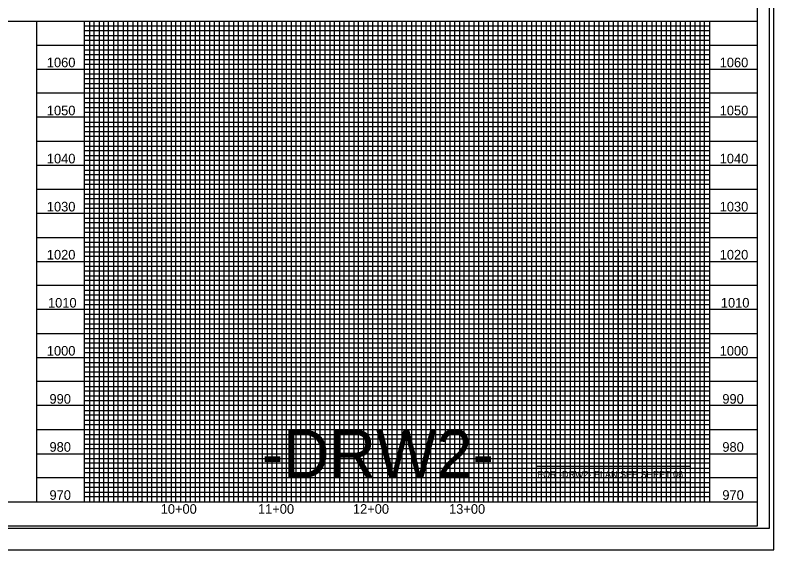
# Model space of a CAD drawing. Extents: x 1260439 to 1262228, y 742196 to 743296.
# Drawn here: x 1261333 to 1262123, y 742196 to 742752 of the extents above; entities that cross this region are included whole.
import ezdxf

# ---------------------------------------------------------------- set-up
doc = ezdxf.new("R2010")
doc.units = 0
for name, color, linetype in [('Exist Vertical Profile Horizontal Axis Label Major', 7, 'Continuous'), ('Exist Vertical Profile Vertical Axis Label', 7, 'Continuous'), ('Prop Grid Mask', 7, 'Continuous'), ('Prop PFL Text', 7, 'Continuous'), ('Sheet Data Field CELL', 7, 'Continuous'), ('Sheet Plot Border Inside CELL', 7, 'Continuous'), ('Sheet Plot Border Outside CELL', 7, 'Continuous'), ('Sheet Profile CELL', 7, 'Continuous'), ('Sheet Profile Grid Major CELL', 7, 'Continuous'), ('Sheet Profile Grid Middle CELL', 7, 'Continuous'), ('Sheet Profile Grid Minor CELL', 7, 'Continuous')]:
    doc.layers.add(name, color=color, linetype=linetype)

msp = doc.modelspace()

# ---------------------------------------------------------------- linework, layer by layer
at = {"layer": 'Prop Grid Mask'}
msp.add_lwpolyline([(1261875.75, 742282.74), (1262035.75, 742282.74), (1262035.75, 742265.74), (1261875.75, 742265.74)], close=True, dxfattribs=at)
at = {"layer": 'Sheet Plot Border Inside CELL'}
msp.add_lwpolyline([(1260451.75, 742218.19), (1262118.25, 742218.19), (1262118.25, 743273.29), (1260451.75, 743273.29)], close=True, dxfattribs=at)
at = {"layer": 'Sheet Plot Border Outside CELL'}
msp.add_lwpolyline([(1260438.75, 742195.74), (1262122.75, 742195.74), (1262122.75, 743295.74), (1260438.75, 743295.74)], close=True, dxfattribs=at)
at = {"layer": 'Sheet Profile CELL'}
for p, q in [((1260605.75, 742745.74), (1262105.75, 742745.74)), ((1260605.75, 742245.74), (1262105.75, 742245.74))]:
    msp.add_line(p, q, dxfattribs=at)
msp.add_lwpolyline([(1262105.75, 743270.74), (1260605.75, 743270.74), (1260605.75, 742220.74), (1262105.75, 742220.74)], close=True, dxfattribs=at)
at = {"layer": 'Sheet Profile Grid Major CELL'}
for p, q in [((1261305.75, 742745.74), (1261355.75, 742745.74)), ((1261355.75, 742745.74), (1261355.75, 742245.74)), ((1261405.75, 742745.74), (1261455.75, 742745.74)), ((1261405.75, 742245.74), (1261405.75, 742745.74)), ((1261405.75, 742745.74), (1261455.75, 742745.74)), ((1261455.75, 742745.74), (1261455.75, 742245.74)), ((1261505.75, 742745.74), (1261555.75, 742745.74)), ((1261505.75, 742245.74), (1261505.75, 742745.74)), ((1261505.75, 742745.74), (1261555.75, 742745.74)), ((1261555.75, 742745.74), (1261555.75, 742245.74)), ((1261605.75, 742745.74), (1261655.75, 742745.74)), ((1261605.75, 742245.74), (1261605.75, 742745.74)), ((1261605.75, 742745.74), (1261655.75, 742745.74)), ((1261655.75, 742745.74), (1261655.75, 742245.74)), ((1261705.75, 742745.74), (1261755.75, 742745.74)), ((1261705.75, 742245.74), (1261705.75, 742745.74)), ((1261705.75, 742745.74), (1261755.75, 742745.74)), ((1261755.75, 742745.74), (1261755.75, 742245.74)), ((1261805.75, 742745.74), (1261855.75, 742745.74)), ((1261805.75, 742245.74), (1261805.75, 742745.74)), ((1261855.75, 742745.74), (1261855.75, 742245.74)), ((1261905.75, 742745.74), (1261955.75, 742745.74)), ((1261905.75, 742245.74), (1261905.75, 742745.74)), ((1262005.75, 742745.74), (1262055.75, 742745.74)), ((1261355.75, 742245.74), (1261405.75, 742245.74)), ((1261455.75, 742245.74), (1261505.75, 742245.74)), ((1261555.75, 742245.74), (1261605.75, 742245.74)), ((1261655.75, 742245.74), (1261705.75, 742245.74)), ((1261755.75, 742245.74), (1261805.75, 742245.74)), ((1261855.75, 742245.74), (1261905.75, 742245.74))]:
    msp.add_line(p, q, dxfattribs=at)
for points in [[(1261955.75, 742745.74), (1261955.75, 742245.74), (1262005.75, 742245.74), (1262005.75, 742245.74), (1262005.75, 742745.74)], [(1262055.75, 742745.74), (1262055.75, 742245.74), (1262105.75, 742245.74), (1262105.75, 742740.74)], [(1261355.75, 742695.74), (1262105.75, 742695.74)], [(1262105.75, 742645.74), (1261355.75, 742645.74)], [(1261355.75, 742595.74), (1262105.75, 742595.74)], [(1262105.75, 742545.74), (1261355.75, 742545.74)], [(1261355.75, 742495.74), (1262105.75, 742495.74)], [(1262105.75, 742445.74), (1261355.75, 742445.74)], [(1261355.75, 742395.74), (1262105.75, 742395.74)], [(1262105.75, 742345.74), (1261355.75, 742345.74)], [(1261355.75, 742295.74), (1262105.75, 742295.74)]]:
    msp.add_lwpolyline(points, dxfattribs=at)
at = {"layer": 'Sheet Profile Grid Middle CELL'}
for p, q in [((1261430.75, 742245.74), (1261430.75, 742745.74)), ((1261430.75, 742745.74), (1261480.75, 742745.74)), ((1261480.75, 742745.74), (1261480.75, 742245.74)), ((1261530.75, 742245.74), (1261530.75, 742745.74)), ((1261530.75, 742745.74), (1261580.75, 742745.74)), ((1261580.75, 742745.74), (1261580.75, 742245.74)), ((1261630.75, 742245.74), (1261630.75, 742745.74)), ((1261630.75, 742745.74), (1261680.75, 742745.74)), ((1261680.75, 742745.74), (1261680.75, 742245.74)), ((1261730.75, 742245.74), (1261730.75, 742745.74)), ((1261730.75, 742745.74), (1262055.75, 742745.74)), ((1261780.75, 742745.74), (1261780.75, 742245.74)), ((1261830.75, 742245.74), (1261830.75, 742745.74)), ((1261880.75, 742745.74), (1261880.75, 742245.74)), ((1261930.75, 742245.74), (1261930.75, 742745.74)), ((1261355.75, 742720.74), (1262105.75, 742720.74)), ((1261380.75, 742245.74), (1261430.75, 742245.74)), ((1261480.75, 742245.74), (1261530.75, 742245.74)), ((1261580.75, 742245.74), (1261630.75, 742245.74)), ((1261680.75, 742245.74), (1261730.75, 742245.74)), ((1261780.75, 742245.74), (1261830.75, 742245.74)), ((1261880.75, 742245.74), (1261930.75, 742245.74))]:
    msp.add_line(p, q, dxfattribs=at)
for points in [[(1261930.75, 742508.54), (1261930.75, 742245.74), (1261980.75, 742245.74), (1261980.75, 742745.74)], [(1261980.75, 742508.54), (1261980.75, 742245.74), (1262030.75, 742245.74), (1262030.75, 742745.74)], [(1262105.75, 742670.74), (1261355.75, 742670.74)], [(1261355.75, 742620.74), (1262105.75, 742620.74)], [(1262105.75, 742570.74), (1261355.75, 742570.74)], [(1261355.75, 742520.74), (1261930.75, 742520.74)], [(1261930.75, 742520.74), (1262105.75, 742520.74)], [(1262105.75, 742470.74), (1261355.75, 742470.74)], [(1261355.75, 742420.74), (1262105.75, 742420.74)], [(1262105.75, 742370.74), (1261355.75, 742370.74)], [(1261355.75, 742320.74), (1262105.75, 742320.74)], [(1262105.75, 742270.74), (1261355.75, 742270.74)]]:
    msp.add_lwpolyline(points, dxfattribs=at)
at = {"layer": 'Sheet Profile Grid Minor CELL'}
for p, q in [((1261800.75, 742245.74), (1261800.75, 742745.74)), ((1261810.75, 742745.74), (1261810.75, 742245.74)), ((1261815.75, 742245.74), (1261815.75, 742745.74)), ((1261820.75, 742745.74), (1261820.75, 742245.74)), ((1261825.75, 742245.74), (1261825.75, 742745.74)), ((1261835.75, 742745.74), (1261835.75, 742245.74)), ((1261840.75, 742245.74), (1261840.75, 742745.74)), ((1261845.75, 742745.74), (1261845.75, 742245.74)), ((1261850.75, 742245.74), (1261850.75, 742745.74)), ((1261860.75, 742745.74), (1261860.75, 742245.74)), ((1261865.75, 742245.74), (1261865.75, 742745.74)), ((1261870.75, 742745.74), (1261870.75, 742245.74)), ((1261875.75, 742245.74), (1261875.75, 742745.74)), ((1261885.75, 742745.74), (1261885.75, 742245.74)), ((1261890.75, 742245.74), (1261890.75, 742745.74)), ((1261895.75, 742745.74), (1261895.75, 742245.74)), ((1261900.75, 742245.74), (1261900.75, 742745.74)), ((1261405.75, 742740.74), (1262055.75, 742740.74)), ((1262055.75, 742735.78), (1261405.75, 742735.6)), ((1261405.75, 742730.74), (1262055.75, 742730.74)), ((1262055.75, 742610.74), (1261405.75, 742610.74)), ((1262055.75, 742605.74), (1261405.75, 742605.74)), ((1262055.75, 742600.74), (1261405.75, 742600.74)), ((1261405.75, 742590.74), (1262055.75, 742590.74)), ((1262055.75, 742585.74), (1261405.75, 742585.74)), ((1261405.75, 742580.74), (1262055.75, 742580.74)), ((1262055.75, 742560.74), (1261405.75, 742560.74)), ((1261405.75, 742555.74), (1262055.75, 742555.74)), ((1262055.75, 742535.74), (1261405.75, 742535.74)), ((1261405.75, 742530.74), (1262055.75, 742530.74)), ((1262055.75, 742510.74), (1261405.75, 742510.74)), ((1261405.75, 742505.74), (1262055.75, 742505.74)), ((1262055.75, 742500.74), (1261405.75, 742500.74)), ((1261405.75, 742490.74), (1262055.75, 742490.74)), ((1262055.75, 742485.74), (1261405.75, 742485.74)), ((1261405.75, 742480.74), (1262055.75, 742480.74)), ((1262055.75, 742475.74), (1261405.75, 742475.74)), ((1261405.75, 742465.74), (1262055.75, 742465.74)), ((1262055.75, 742460.74), (1261405.75, 742460.74)), ((1261405.75, 742455.74), (1262055.75, 742455.74)), ((1262055.75, 742450.74), (1261405.75, 742450.74)), ((1261405.75, 742440.74), (1262055.75, 742440.74)), ((1262055.75, 742435.74), (1261405.75, 742435.74)), ((1261405.75, 742430.74), (1262055.75, 742430.74)), ((1262055.75, 742425.74), (1261405.75, 742425.74)), ((1261405.75, 742415.74), (1262055.75, 742415.74)), ((1262055.75, 742410.74), (1261405.75, 742410.74)), ((1261405.75, 742405.74), (1262055.75, 742405.74)), ((1262055.75, 742400.74), (1261405.75, 742400.74)), ((1261405.75, 742390.74), (1262055.75, 742390.74)), ((1262055.75, 742385.74), (1261405.75, 742385.74)), ((1261405.75, 742380.74), (1262055.75, 742380.74)), ((1262055.75, 742375.74), (1261405.75, 742375.74)), ((1261405.75, 742365.74), (1262055.75, 742365.74)), ((1262055.75, 742360.74), (1261405.75, 742360.74)), ((1262055.75, 742355.74), (1261405.75, 742355.74)), ((1262055.75, 742350.74), (1261405.75, 742350.74)), ((1261405.75, 742340.74), (1262055.75, 742340.74)), ((1262055.75, 742335.74), (1261405.75, 742335.74)), ((1261405.75, 742330.74), (1262055.75, 742330.74)), ((1262055.75, 742325.74), (1261405.75, 742325.74)), ((1261405.75, 742315.74), (1262055.75, 742315.74)), ((1262055.75, 742310.74), (1261405.75, 742310.74)), ((1261405.75, 742305.74), (1262055.75, 742305.74)), ((1262055.75, 742300.74), (1261405.75, 742300.74)), ((1261405.75, 742290.74), (1262055.75, 742290.74)), ((1262055.75, 742285.74), (1261405.75, 742285.74)), ((1261405.75, 742280.74), (1262055.75, 742280.74)), ((1262055.75, 742275.74), (1261405.75, 742275.74)), ((1261405.75, 742265.74), (1262055.75, 742265.74)), ((1262055.75, 742260.74), (1261405.75, 742260.74)), ((1261405.75, 742255.74), (1262055.75, 742255.74)), ((1261795.75, 742245.74), (1261800.75, 742245.74)), ((1261810.75, 742245.74), (1261815.75, 742245.74)), ((1261820.75, 742245.74), (1261825.75, 742245.74)), ((1261835.75, 742245.74), (1261840.75, 742245.74)), ((1261845.75, 742245.74), (1261850.75, 742245.74)), ((1261860.75, 742245.74), (1261865.75, 742245.74)), ((1261870.75, 742245.74), (1261875.75, 742245.74)), ((1261885.75, 742245.74), (1261890.75, 742245.74)), ((1261895.75, 742245.74), (1261900.75, 742245.74))]:
    msp.add_line(p, q, dxfattribs=at)
for points in [[(1261405.75, 742745.74), (1261410.75, 742745.74), (1261410.75, 742245.74), (1261415.75, 742245.74), (1261415.75, 742745.74), (1261420.75, 742745.74), (1261420.75, 742245.74), (1261425.75, 742245.74), (1261425.75, 742745.74), (1261435.75, 742745.74), (1261435.75, 742245.74), (1261440.75, 742245.74), (1261440.75, 742745.74), (1261445.75, 742745.74), (1261445.75, 742245.74), (1261450.75, 742245.74), (1261450.75, 742745.74), (1261460.75, 742745.74), (1261460.75, 742245.74), (1261465.45, 742246.29), (1261465.75, 742245.74), (1261465.75, 742745.74), (1261470.75, 742745.74), (1261470.75, 742245.74), (1261475.75, 742245.74), (1261475.75, 742745.74), (1261485.75, 742745.74), (1261485.75, 742245.74), (1261490.75, 742245.74)], [(1261490.75, 742245.74), (1261490.75, 742745.74), (1261495.75, 742745.74), (1261495.75, 742245.74), (1261500.75, 742245.74), (1261500.75, 742745.74), (1261510.75, 742745.74), (1261510.75, 742245.74), (1261515.75, 742245.74), (1261515.75, 742745.74), (1261520.75, 742745.74), (1261520.75, 742245.74), (1261525.75, 742245.74), (1261525.75, 742745.74), (1261535.75, 742745.74), (1261535.75, 742245.74), (1261540.75, 742245.74), (1261540.75, 742745.74), (1261545.75, 742745.74), (1261545.75, 742245.74), (1261550.75, 742245.74), (1261550.75, 742745.74), (1261560.75, 742745.74), (1261560.75, 742245.74), (1261565.75, 742245.74), (1261565.75, 742745.74), (1261570.75, 742745.74), (1261570.75, 742245.74), (1261575.75, 742245.74), (1261575.75, 742745.74), (1261585.75, 742745.74), (1261585.75, 742245.74), (1261590.75, 742245.74), (1261590.75, 742745.74), (1261595.75, 742745.74), (1261595.75, 742245.74), (1261600.75, 742245.74), (1261600.75, 742745.74), (1261610.75, 742745.74), (1261610.75, 742245.74), (1261615.75, 742245.74), (1261615.75, 742745.74), (1261620.75, 742745.74), (1261620.75, 742245.74), (1261625.75, 742245.74), (1261625.75, 742745.74), (1261635.75, 742745.74), (1261635.75, 742245.74), (1261640.75, 742245.74), (1261640.75, 742745.74), (1261645.75, 742745.74), (1261645.75, 742245.74), (1261650.75, 742245.74), (1261650.75, 742745.74), (1261660.75, 742745.74), (1261660.75, 742245.74), (1261665.75, 742245.74), (1261665.75, 742745.74), (1261670.75, 742745.74), (1261670.75, 742245.74), (1261675.75, 742245.74), (1261675.75, 742745.74), (1261685.75, 742745.74), (1261685.75, 742245.74), (1261690.75, 742245.74), (1261690.75, 742745.74), (1261695.75, 742745.74), (1261695.75, 742245.74), (1261700.75, 742245.74), (1261700.75, 742745.74), (1261710.75, 742745.74), (1261710.75, 742245.74), (1261715.75, 742245.74), (1261715.75, 742745.74), (1261720.75, 742745.74), (1261720.75, 742245.74), (1261725.75, 742245.74), (1261725.75, 742745.74), (1261735.75, 742745.74), (1261735.75, 742245.74), (1261740.75, 742245.74), (1261740.75, 742745.74), (1261745.75, 742745.74), (1261745.75, 742245.74), (1261750.75, 742245.74), (1261750.75, 742745.74), (1261760.75, 742745.74), (1261760.75, 742245.74), (1261765.75, 742245.74), (1261765.75, 742745.74), (1261770.75, 742745.74), (1261770.75, 742245.74), (1261775.75, 742245.74), (1261775.75, 742745.74), (1261785.75, 742745.74), (1261785.75, 742245.74), (1261790.75, 742245.74), (1261790.75, 742745.74), (1261795.75, 742745.74), (1261795.75, 742245.74)], [(1261910.75, 742745.74), (1261910.75, 742245.74), (1261915.75, 742245.74), (1261915.75, 742745.74)], [(1261920.75, 742745.74), (1261920.75, 742245.74), (1261925.75, 742245.74), (1261925.75, 742745.74)], [(1261935.75, 742745.74), (1261935.75, 742245.74), (1261935.75, 742245.74), (1261940.75, 742245.74), (1261945.75, 742245.74), (1261945.75, 742745.74)], [(1261940.75, 742745.74), (1261940.75, 742245.74)], [(1261950.79, 742745.74), (1261950.65, 742245.79), (1261955.65, 742245.79), (1261960.75, 742245.74), (1261960.75, 742745.74)], [(1261960.75, 742508.54), (1261960.75, 742245.74), (1261965.75, 742245.74), (1261965.75, 742745.74)], [(1261970.75, 742745.74), (1261970.75, 742245.74), (1261975.75, 742245.74), (1261975.75, 742745.74)], [(1261985.75, 742745.74), (1261985.75, 742245.74), (1261990.75, 742245.74), (1261990.75, 742745.74)], [(1261995.75, 742745.74), (1261995.75, 742245.74), (1262000.75, 742245.74), (1262000.75, 742745.74)], [(1262010.75, 742745.74), (1262010.75, 742245.74), (1262015.75, 742245.74), (1262015.75, 742745.74)], [(1262020.75, 742745.74), (1262020.75, 742245.74), (1262025.75, 742245.74), (1262025.75, 742745.74)], [(1262035.75, 742745.74), (1262035.75, 742245.74), (1262040.75, 742245.74), (1262040.75, 742745.74)], [(1262045.75, 742745.74), (1262045.75, 742245.74), (1262050.75, 742245.74), (1262050.75, 742745.74)], [(1262055.75, 742725.74), (1261405.75, 742725.74)], [(1261405.75, 742715.74), (1262055.75, 742715.74)], [(1262055.75, 742710.74), (1261405.75, 742710.74)], [(1261405.75, 742705.74), (1262055.75, 742705.74)], [(1262055.75, 742700.74), (1261405.75, 742700.74)], [(1261405.75, 742690.74), (1262055.75, 742690.74)], [(1262055.75, 742685.74), (1261405.75, 742685.74)], [(1261405.75, 742680.74), (1262055.75, 742680.74)], [(1262055.75, 742675.74), (1261405.75, 742675.74)], [(1261405.75, 742665.74), (1262055.75, 742665.74)], [(1262055.75, 742660.74), (1261405.75, 742660.74)], [(1261405.75, 742655.74), (1262055.75, 742655.74)], [(1262055.75, 742650.74), (1261405.75, 742650.74)], [(1261405.75, 742640.74), (1262055.75, 742640.74)], [(1262055.75, 742635.64), (1261405.75, 742635.64)], [(1261405.75, 742630.74), (1262055.75, 742630.74)], [(1262055.75, 742625.74), (1261405.75, 742625.74)], [(1261405.75, 742615.74), (1262055.75, 742615.74)], [(1262055.75, 742575.74), (1261405.75, 742575.74)], [(1261405.75, 742565.74), (1262055.75, 742565.74)], [(1262055.75, 742550.74), (1261405.75, 742550.74)], [(1261405.75, 742540.74), (1262055.75, 742540.74)], [(1262055.75, 742525.74), (1261405.75, 742525.74)], [(1261405.75, 742515.74), (1262055.75, 742515.74)], [(1262055.75, 742250.74), (1261405.75, 742250.74)]]:
    msp.add_lwpolyline(points, dxfattribs=at)

# ---------------------------------------------------------------- texts
at = {"layer": 'Exist Vertical Profile Horizontal Axis Label Major'}
for s, p in [('10+00', (1261484.88, 742233.24)), ('11+00', (1261586.08, 742233.24)), ('12+00', (1261684.88, 742233.24)), ('13+00', (1261784.88, 742233.24))]:
    msp.add_text(s, height=10, dxfattribs=at).set_placement(p)
at = {"layer": 'Exist Vertical Profile Vertical Axis Label'}
for s, p in [('1060', (1261366.43, 742697.74)), ('1060', (1262066.43, 742697.74)), ('1050', (1261366.43, 742647.74)), ('1050', (1262066.43, 742647.74)), ('1040', (1261366.43, 742597.74)), ('1040', (1262066.43, 742597.74)), ('1030', (1261366.43, 742547.74)), ('1030', (1262066.43, 742547.74)), ('1020', (1261366.43, 742497.74)), ('1020', (1262066.43, 742497.74)), ('1010', (1261367.63, 742447.74)), ('1010', (1262067.63, 742447.74)), ('1000', (1261366.43, 742397.74)), ('1000', (1262066.43, 742397.74)), ('990', (1261369.19, 742347.74)), ('990', (1262069.19, 742347.74)), ('980', (1261369.19, 742297.74)), ('980', (1262069.19, 742297.74)), ('970', (1261369.19, 742247.74)), ('970', (1262069.19, 742247.74))]:
    msp.add_text(s, height=10, dxfattribs=at).set_placement(p)
at = {"layer": 'Prop PFL Text'}
msp.add_text('FOR -DRW2- PLAN SEE SHEET 06', height=7, dxfattribs=at).set_placement((1261876.98, 742270.74))
at = {"layer": 'Sheet Data Field CELL'}
msp.add_text('-DRW2-', height=50, dxfattribs=at).set_placement((1261590, 742270.74))

doc.saveas('drawing.dxf')
